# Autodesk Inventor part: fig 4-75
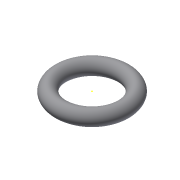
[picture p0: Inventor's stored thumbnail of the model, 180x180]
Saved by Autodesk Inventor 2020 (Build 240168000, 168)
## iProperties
Created: 2012-07
Part Number: fig 4-75
Material: Generic
Document SubType Name: Modeling
Designer: CADCIM
Density: 1 g/cm^3
Appearance: Default
Author: CADCIM
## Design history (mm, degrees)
sketch "Sketch2"
  geometry: 1 further point
  constraints: 1 other
feature "Form2"
body "Solid1"
body "Solid3"
